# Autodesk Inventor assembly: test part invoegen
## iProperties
Created: 2009-12
Part Number: test part invoegen
Document SubType Name: Assembly
Designer: Guido
Mass: 23.0365 g
Surface Area: 76.2832 cm^2
Volume: 23.0365 cm^3
Density: 1 g/cm^3
Author: Guido
